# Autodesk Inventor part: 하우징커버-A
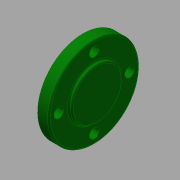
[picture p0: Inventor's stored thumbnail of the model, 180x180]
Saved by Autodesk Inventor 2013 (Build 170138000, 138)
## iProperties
Created: 2018-01
Part Number: 하우징커버-A
Material: 알루미늄 6061
Document SubType Name: Modeling
Designer: mduedu
Density: 2.71 g/cm^3
Mass: 8.99967 g
Surface Area: 21.1948 cm^2
Volume: 3.32091 cm^3
Author: mduedu
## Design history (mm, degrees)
sketch "스케치1"
  geometry: C1 r 16 at (0, 0); 1 further point
  constraints: 1 centre point, 1 coincident
  dimensions: "d0" = 32 diameter of C1
extrude "돌출1" new body sketch "스케치1" distance "d1" = 4; taper "d2" = 0 deg
sketch "스케치2"
  geometry: C1 r 9 at (0, 0); 1 further point
  constraints: 1 centre point, 1 coincident
  dimensions: "d3" = 18 diameter of C1
extrude "돌출2" join sketch "스케치2" distance "d4" = 1; taper "d5" = 0 deg
fillet "모깎기1" dims "d6" = 0.5
fillet "모깎기2" dims "d7" = 0.5
sketch "스케치3" dims "d8" = 25
  geometry: 6 further points
  constraints: 2 vertical alignment, 1 coincident, 7 other
  dimensions: "d11" = 360 deg dimension on point (0, 0) point (0, 12.5) (derived)
sketch "스케치4"
  geometry: 4 further points
  constraints: 4 other
hole "구멍1" sketch "스케치4" at (-12.5, 0), (0, -12.5), (12.5, 0), (0, 12.5) diameter "d13" = 3.4; stored, may be unused: countersink angle "d17" = 90 deg, drill point angle "d19" = 0 deg; dims "d14" = 6, "d15" = 4, "d16" = 2, "d18" = 8
node "솔리드1"
